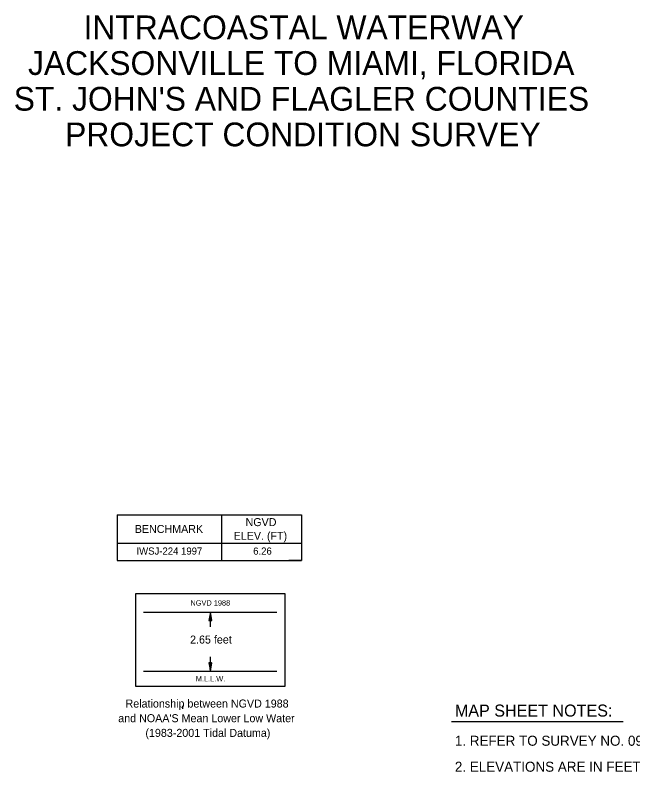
# Model space of a CAD drawing. Extents: x 565003 to 644146, y 1916234 to 1975957.
# Drawn here: x 597282 to 620356, y 1947675 to 1975957 of the extents above; entities that cross this region are included whole.
import ezdxf

# ---------------------------------------------------------------- set-up
doc = ezdxf.new("R2010")
doc.units = 0
for name, color, linetype in [('C-TAXI-CNTR', 7, 'Continuous'), ('C-TAXI-CNTR-IDEN', 7, 'Continuous'), ('C-TAXI-CNTR-MRKG', 7, 'Continuous'), ('C-TAXI-HOLD', 7, 'Continuous'), ('C-TAXI-IDEN', 7, 'Continuous'), ('C-TAXI-SHLD', 7, 'Continuous')]:
    doc.layers.add(name, color=color, linetype=linetype)

msp = doc.modelspace()

# ---------------------------------------------------------------- linework, layer by layer
at = {"layer": 'C-TAXI-CNTR-IDEN'}
msp.add_line((613586, 1949556), (619999, 1949556), dxfattribs=at)
at = {"layer": 'C-TAXI-CNTR-MRKG'}
for p, q in [((602082, 1953641), (607063, 1953639)), ((604574, 1953093), (604574, 1953640)), ((604574, 1951438), (604574, 1951974)), ((602082, 1951438), (607063, 1951438))]:
    msp.add_line(p, q, dxfattribs=at)
for points in [[(601795, 1954339), (607353, 1954339)], [(601795, 1950870), (601795, 1954339)], [(607353, 1954339), (607353, 1950870)], [(604522, 1953329), (604527, 1953331), (604534, 1953334), (604542, 1953336), (604547, 1953338), (604553, 1953339), (604558, 1953340), (604562, 1953340), (604566, 1953341), (604569, 1953341), (604575, 1953341), (604582, 1953341), (604588, 1953340), (604594, 1953339), (604602, 1953338), (604610, 1953335), (604617, 1953333), (604622, 1953331), (604626, 1953329), (604574, 1953640), (604522, 1953329), (604534, 1953346), (604610, 1953350), (604575, 1953583), (604534, 1953346), (604549, 1953359), (604596, 1953366), (604574, 1953529), (604549, 1953359), (604559, 1953373), (604585, 1953380), (604574, 1953474), (604559, 1953373), (604569, 1953385), (604579, 1953389), (604574, 1953426), (604569, 1953385)], [(604626, 1951750), (604620, 1951747), (604613, 1951744), (604606, 1951742), (604600, 1951741), (604594, 1951739), (604590, 1951738), (604585, 1951738), (604582, 1951738), (604578, 1951737), (604573, 1951737), (604566, 1951738), (604559, 1951738), (604554, 1951739), (604546, 1951741), (604537, 1951744), (604531, 1951746), (604526, 1951748), (604522, 1951750), (604574, 1951438), (604626, 1951750), (604613, 1951732), (604538, 1951728), (604573, 1951495), (604613, 1951732), (604599, 1951720), (604552, 1951712), (604574, 1951549), (604599, 1951720), (604588, 1951705), (604562, 1951699), (604574, 1951604), (604588, 1951705), (604579, 1951694), (604568, 1951689), (604574, 1951652), (604579, 1951694)], [(607353, 1950870), (601795, 1950870)]]:
    msp.add_lwpolyline(points, dxfattribs=at)
at = {"layer": 'C-TAXI-HOLD'}
for p, q in [((601099, 1957286), (601099, 1955579)), ((601099, 1957286), (607974, 1957286)), ((604987, 1957286), (604987, 1955579)), ((607975, 1957286), (607974, 1955579)), ((601099, 1956219), (607974, 1956219)), ((601099, 1955579), (607974, 1955579))]:
    msp.add_line(p, q, dxfattribs=at)
at = {"layer": 'C-TAXI-IDEN'}
msp.add_line((607974, 1955579), (607504, 1955579), dxfattribs=at)
at = {"layer": 'C-TAXI-SHLD'}
msp.add_line((603537, 1950147), (603538, 1950027), dxfattribs=at)

# ---------------------------------------------------------------- texts
at = {"layer": 'C-TAXI-CNTR'}
msp.add_text(' 2.65 feet', height=299.1, rotation=360, dxfattribs=at).set_placement((603706, 1952470))
at = {"layer": 'C-TAXI-CNTR-IDEN'}
for s, height, p in [('MAP SHEET NOTES:', 450.02, (613708, 1949741)), ('1. REFER TO SURVEY NO. 09-119.', 375.02, (613708, 1948651)), ('2. ELEVATIONS ARE IN FEET AND TENTHS AND REFER TO THE NOAA REPORTED', 375.02, (613708, 1947680))]:
    msp.add_text(s, height=height, dxfattribs=at).set_placement(p)
at = {"layer": 'C-TAXI-CNTR-MRKG'}
for s, p in [('INTRACOASTAL WATERWAY', (599838, 1975054)), ('JACKSONVILLE TO MIAMI, FLORIDA', (597762, 1973721)), ("ST. JOHN'S AND FLAGLER COUNTIES", (597228, 1972387)), ('PROJECT CONDITION SURVEY', (599148, 1971054))]:
    msp.add_text(s, height=888.98, dxfattribs=at).set_placement(p)
for s, height, rotation, p in [('NGVD 1988', 199.3, 359.9958, (603830, 1953890)), ('M.L.L.W.', 199.3, 359.9958, (604030, 1951054)), ('Relationship between NGVD 1988', 299.06, 360, (601406, 1950079)), ("and NOAA'S Mean Lower Low Water", 299.06, 360, (601134, 1949531)), ('(1983-2001 Tidal Datuma)', 299.06, 360, (602148, 1948983))]:
    msp.add_text(s, height=height, rotation=rotation, dxfattribs=at).set_placement(p)
at = {"layer": 'C-TAXI-HOLD'}
for s, height, p in [('NGVD', 298.7, (605889, 1956859)), ('BENCHMARK', 298.7, (601751, 1956603)), ('ELEV. (FT)', 298.7, (605445, 1956347)), (' IWSJ-224 1997', 266.69, (601716, 1955794)), (' 6.26', 266.7, (606075, 1955794))]:
    msp.add_text(s, height=height, rotation=360, dxfattribs=at).set_placement(p)

doc.saveas('drawing.dxf')
